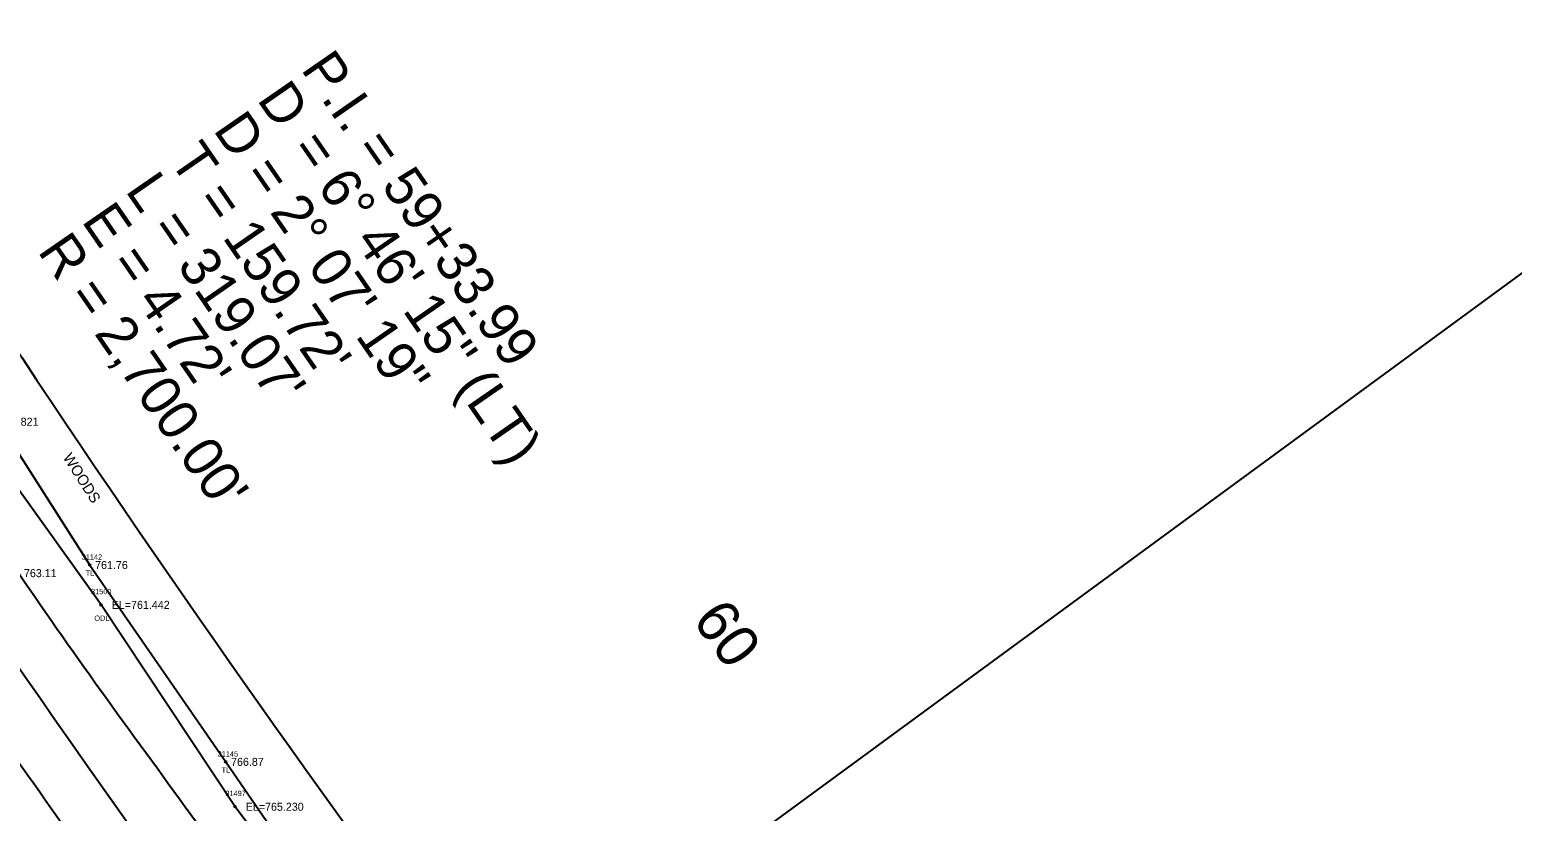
# Model space of a CAD drawing. Extents: x 1375131 to 1378678, y 999028 to 1004053.
# Drawn here: x 1378040.5 to 1378318.5, y 1000535.2 to 1000681.6 of the extents above; entities that cross this region are included whole.
import ezdxf

# ---------------------------------------------------------------- set-up
doc = ezdxf.new("R2010")
doc.units = 0
for name, color, linetype in [('RD_EX_DV_Prop', 7, 'Continuous'), ('RD_EX_H2O', 7, 'Continuous'), ('RD_EX_H2O_txCode', 7, 'Continuous'), ('RD_EX_Road', 7, 'Continuous'), ('RD_EX_RW', 7, 'Continuous'), ('RD_EX_TX_H2O_ELEV', 7, 'Continuous'), ('RD_EX_TX_Road_ELEV', 7, 'Continuous'), ('RD_EX_TX_VEG_ELEV', 7, 'Continuous'), ('RD_EX_VEG', 7, 'Continuous'), ('RD_EX_VEG_txCode', 7, 'Continuous'), ('RD_HC_Cl', 7, 'Continuous'), ('RD_HC_Data', 7, 'Continuous'), ('RD_HC_TX_Sta50', 7, 'Continuous'), ('RD_SMD_Locator', 7, 'Continuous'), ('RD_TX_Misc2', 7, 'Continuous')]:
    doc.layers.add(name, color=color, linetype=linetype)

msp = doc.modelspace()

# ---------------------------------------------------------------- linework, layer by layer
at = {"layer": 'RD_EX_DV_Prop'}
msp.add_line((1378127.6, 1000494.84), (1378498.59, 1000766.64), dxfattribs=at)
at = {"layer": 'RD_EX_H2O'}
msp.add_lwpolyline([(1378187.96, 1000391.62), (1378166.95, 1000418.07), (1378136.83, 1000457.58), (1378104.58, 1000501.86), (1378079.02, 1000536.04), (1378053.9, 1000573.86), (1378029.31, 1000608.17), (1378022.93, 1000618.73)], dxfattribs=at)
at = {"layer": 'RD_EX_Road'}
for points in [[(1378177.15, 1000392.85), (1378139.73, 1000441.52), (1378104.67, 1000487.69), (1378071.79, 1000533.09), (1378038.45, 1000579.8), (1378007.55, 1000627.96), (1377974.27, 1000678.86), (1377944.47, 1000727.12), (1377913.03, 1000778.58), (1377899.67, 1000800.29)], [(1378161.36, 1000381.16), (1378123.91, 1000428.54), (1378087.58, 1000476.32), (1378055.08, 1000520.94), (1378021.67, 1000568.71), (1377989.95, 1000617.08), (1377957.33, 1000668.38), (1377927.53, 1000716.55), (1377895.41, 1000768.82), (1377883.75, 1000788.5)]]:
    msp.add_spline(points, degree=3, dxfattribs=at)
at = {"layer": 'RD_EX_RW'}
for radius in [2667, 2733]:
    msp.add_arc((1380260.77, 1002095.62), radius, 211.36799, 218.13892, dxfattribs=at)
at = {"layer": 'RD_EX_VEG'}
msp.add_lwpolyline([(1377975.86, 1000867.47), (1377940.96, 1000846.12), (1377905.66, 1000824.77), (1377936.14, 1000772.34), (1377973.26, 1000709.66), (1378011.8, 1000643.94), (1378051.79, 1000581.32), (1378077.27, 1000544.45), (1378109.04, 1000498.32), (1378149.58, 1000443.93), (1378185.36, 1000398.58)], dxfattribs=at)
at = {"layer": 'RD_HC_Cl'}
msp.add_arc((1380260.77, 1002095.62), 2700, 211.36799, 218.13892, dxfattribs=at)
at = {"layer": 'RD_SMD_Locator'}
for centre in [(1378051.79, 1000581.32), (1378053.9, 1000573.86), (1378077.27, 1000544.45), (1378079.02, 1000536.04)]:
    msp.add_circle(centre, 0.15, dxfattribs=at)

# ---------------------------------------------------------------- texts
at = {"layer": 'RD_EX_H2O_txCode'}
for s, p in [('31500', (1378052.02, 1000575.86)), ('ODL', (1378052.65, 1000570.86)), ('31497', (1378077.22, 1000538.04))]:
    msp.add_text(s, height=1, dxfattribs=at).set_placement(p)
at = {"layer": 'RD_EX_TX_H2O_ELEV'}
for s, p in [('EL=758.821', (1378031.31, 1000607.42)), ('EL=761.442', (1378055.9, 1000573.11)), ('EL=765.230', (1378081.02, 1000535.29))]:
    msp.add_text(s, height=1.5, dxfattribs=at).set_placement(p)
at = {"layer": 'RD_EX_TX_Road_ELEV'}
msp.add_text('763.11', height=1.5, dxfattribs=at).set_placement((1378039.45, 1000579.05))
at = {"layer": 'RD_EX_TX_VEG_ELEV'}
for s, p in [('761.76', (1378052.79, 1000580.57)), ('766.87', (1378078.27, 1000543.7))]:
    msp.add_text(s, height=1.5, dxfattribs=at).set_placement(p)
at = {"layer": 'RD_EX_VEG_txCode'}
for s, p in [('31142', (1378050.28, 1000582.32)), ('TL', (1378051.02, 1000579.32)), ('31145', (1378075.76, 1000545.45)), ('TL', (1378076.5, 1000542.45))]:
    msp.add_text(s, height=1, dxfattribs=at).set_placement(p)
at = {"layer": 'RD_HC_Data'}
for s, p in [('P.I. = 59+33.99', (1378091.25, 1000674.2)), ('D', (1378083.02, 1000668.52)), ('D = 2%%d 07\' 19"', (1378074.8, 1000662.83)), ('    = 6%%d 46\' 15" (LT)', (1378083.02, 1000668.52)), ("T = 159.72'", (1378066.57, 1000657.14)), ("L = 319.07'", (1378058.34, 1000651.46)), ("E = 4.72'", (1378050.12, 1000645.77)), ("R = 2,700.00'", (1378041.89, 1000640.09))]:
    msp.add_text(s, height=7.5, rotation=304.6507, dxfattribs=at).set_placement(p)
at = {"layer": 'RD_HC_TX_Sta50'}
msp.add_text('60', height=8, rotation=306.1582, dxfattribs=at).set_placement((1378164.59, 1000570.98))
at = {"layer": 'RD_TX_Misc2'}
msp.add_text('WOODS', height=2, rotation=302.3586, dxfattribs=at).set_placement((1378046.69, 1000601.49))

doc.saveas('drawing.dxf')
